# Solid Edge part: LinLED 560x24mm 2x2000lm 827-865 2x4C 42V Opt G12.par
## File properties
Author: robert.pupel
Template: iso metric part.par
Last saved by: robert.pupel
Revision: 1
Application: Solid Edge
Gęstość: 0,000 kg/m^3
Dokładność: 0,990
Username: robert.pupel
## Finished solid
Body 1: solid body, 3746 faces, 9636 edges, 6152 vertices.
  Faces by surface: plane 2576, cylinder 530, spline 384, cone 120, sphere 64, torus 40, spun 32
  Edges by curve: line 7152, curve on surface 1296, circle 708, ellipse 264, spline 200, intersection 16
Bounding box of the edges (mm; curved faces can reach further): 559.500 x 4.450 x 24.000, from (-279.75, -4.45, -12) to (279.75, 0, 12).
Cylindrical faces by radius (mm): R0.2 x184, R0.2169 x24, R0.25 x64, R0.3373 x24, R0.4 x32, R0.4006 x8, R0.4008 x8, R0.525 x8, R0.6 x80, R1 x32, R1.1 x16, R1.2 x40, R2.15 x10
Conical faces (half-angle, radius in mm at the cone's reference point): 0.5 deg R0.5056 x16, 0.5 deg R1.0082 x16, 1 deg R0.5511 x8, 10 deg R0.2132 x16, 10 deg R0.4132 x16, 18.8604 deg R1.0669 x16, 27.363 deg R0.6214 x8, 45 deg R0.575 x8, 45 deg R0.625 x16
Toroidal faces (ring radius, tube radius in mm): R0.8 r0.2 x16, R0.8522 r0.3 x8, R0.9002 r0.2 x8, R0.9018 r0.2 x8
Spherical faces by radius (mm): R0.2 x48, R0.6 x16
Planar faces by outward normal: +x 291, +y 33, +z 295, -x 291, -y 433, -z 301, oblique 932
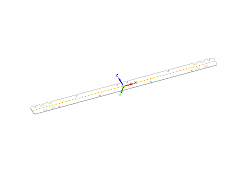
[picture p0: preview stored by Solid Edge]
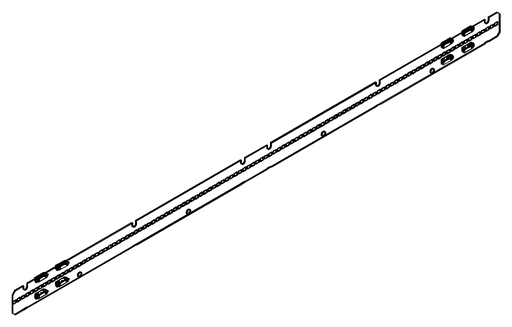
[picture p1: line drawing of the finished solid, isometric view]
